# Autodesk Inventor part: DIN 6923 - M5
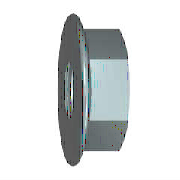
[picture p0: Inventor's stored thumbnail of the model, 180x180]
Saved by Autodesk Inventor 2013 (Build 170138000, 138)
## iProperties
Created: 2012-02
Part Number: DIN 6923 - M5
Material: Stahl, weich
Description: Sechskantmutter
Document SubType Name: Modeling
Standard: DIN 6923
Designer: Dan
Standards Organization: DIN
Language: de-DE
Size Designation: M5
Categories: <MemberInstance><Categories><Category DisplayName="Verbindungselemente" InternalName="e4da775c-781d-43d5-af7c-5136215cf5a6" Mnemonic="FSTN"><Category DisplayNam
Density: 1 g/cm^3
IsCustomPart: 0
Author: Dan
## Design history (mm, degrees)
sketch "Skizze1"
  geometry: L1 (-1.204, 0)-(6.034, 0) reference; L2 (2.523, 4)-(1.906, 5.323); L3 (2.523, 4)-(5, 4); L4 (5, 4)-(5, 0); L5 (2.523, 4)-(2.523, 0); L6 (0, -1.218)-(0, 7.305) reference; A1 r 1 centre (1, 4.9) between (1.906, 5.323) and (0, 4.9); 1 further point
  constraints: 8 end point, 3 point on line, 2 perpendicular, 2 point on circle, 2 tangent, 1 centre point, 1 parallel
  dimensions: "d2" = 8 diameter of L3 L1 (= SW); "d4" = 11.8 dimension on A1 L1 (= LADI); "d5" = 1 radius of A1 (= PHH); "d15" = 5 distance between parallel lines of L4 L6 (= KOH); "d16" = 25 deg angle of L6 L2 (= KEWI)
revolve "Ring" sketch "Skizze1" stored, may be unused: angle "d8" = 90 deg
sketch "Skizze2"
  geometry: L1 (-4, -2.309)-(-4, 2.309); L2 (-4, 2.309)-(0, 4.619); L3 (0, 4.619)-(4, 2.309); L4 (4, 2.309)-(4, -2.309); L5 (4, -2.309)-(0, -4.619); L6 (0, -4.619)-(-4, -2.309); C1 r 4.9 at (0, 0); C2 r 4.9 at (0, 0) reference; 1 further point
  constraints: 12 end point, 1 centre point, 1 coincident, 1 vertical, 11 other
  dimensions: "d6" = 9.2376 distance of L5.end L2.end (= 1.1547 x SW)
extrude "Körper" join sketch "Skizze2" distance "d7" = 5 (= KOH); taper "d9" = 0 deg
sketch "Skizze3"
  geometry: L1 (2.235, 4.619)-(5, 4.619) reference; L2 (5, 2.309)-(5, 4.619) reference; L3 (0, -4.9)-(0, 4.9) reference; L4 (-1, 0)-(6, 0) reference; L5 (4.834, 4.619)-(5, 4)
  constraints: 2 end point, 2 point on line
  dimensions: "d10" = 15 deg angle of L2 L5 (= ANG1); "d11" = 8 diameter of L5.end L4 (= SW0)
revolve "Fase1" sketch "Skizze3" stored, may be unused: angle "d24" = 90 deg
sketch "Skizze4"
  geometry: C1 r 4.9 at (0, 0) reference; 1 further point
  constraints: 1 coincident
hole "Gewinde" sketch "Skizze4" at (0, 0) diameter "d25" = 4.134; stored, may be unused: countersink angle "d29" = 82 deg, drill point angle "d31" = 118 deg; dims "d26" = 6, "d27" = 4, "d28" = 2, "d30" = 8
workaxis "Work Axis1"
workplane "Work Plane1"
body "Solid1"
chamfer "Fase2" distance "d12" = 0.43301 (= -0.5 x GD1 + 0.5 x NND); stored, may be unused: angle "d13" = 30 deg, second distance "d46" = 0.43301 (= -0.5 x GD1 + 0.5 x NND)
chamfer "Fase3" distance "d51" = 0.43301 (= -0.5 x GD1 + 0.5 x NND); stored, may be unused: second distance "d52" = 2, angle "d53" = 45 deg
other parameters: "ANG1" = 15 deg [user parameter; used in 1 equation term], "KEWI" = 25 deg [user parameter; used in 1 equation term], "NND" = 5 [user parameter; used in 4 equation terms], "LADI" = 11.8 [user parameter; used in 2 equation terms], "SW" = 8 [user parameter; used in 4 equation terms], "PHH" = 1 (= RR) [user parameter; used in 2 equation terms], "KOH" = 5 (= NND) [user parameter; used in 2 equation terms], "SW0" = 8 (= SW) [user parameter; used in 1 equation term], "GD1" = 4.13397 (computed from THREADDIA, PTC, TOA) [user parameter; used in 3 equation terms], "d1" = 11.8 (= LADI), "d3" = 1 (= PHH), "d45" = 0, "d47" = 0, "d49" = 0, "d54" = 0, "GUL" = 0.43301 (= 0.541266 x PTC) [user parameter], "TPU" = 12.5 (computed from PTC) [user parameter], "RR" = 1 [user parameter; used in 1 equation term], "THREADDIA" = 5 [user parameter; used in 1 equation term], "TOA" = 30 deg [user parameter; used in 1 equation term], "PTC" = 0.8 [user parameter; used in 4 equation terms], "GAL" = 0.43301 (= 0.541266 x PTC) [user parameter], "E0" = 9.24 (= 1.155 x SW) [user parameter]
